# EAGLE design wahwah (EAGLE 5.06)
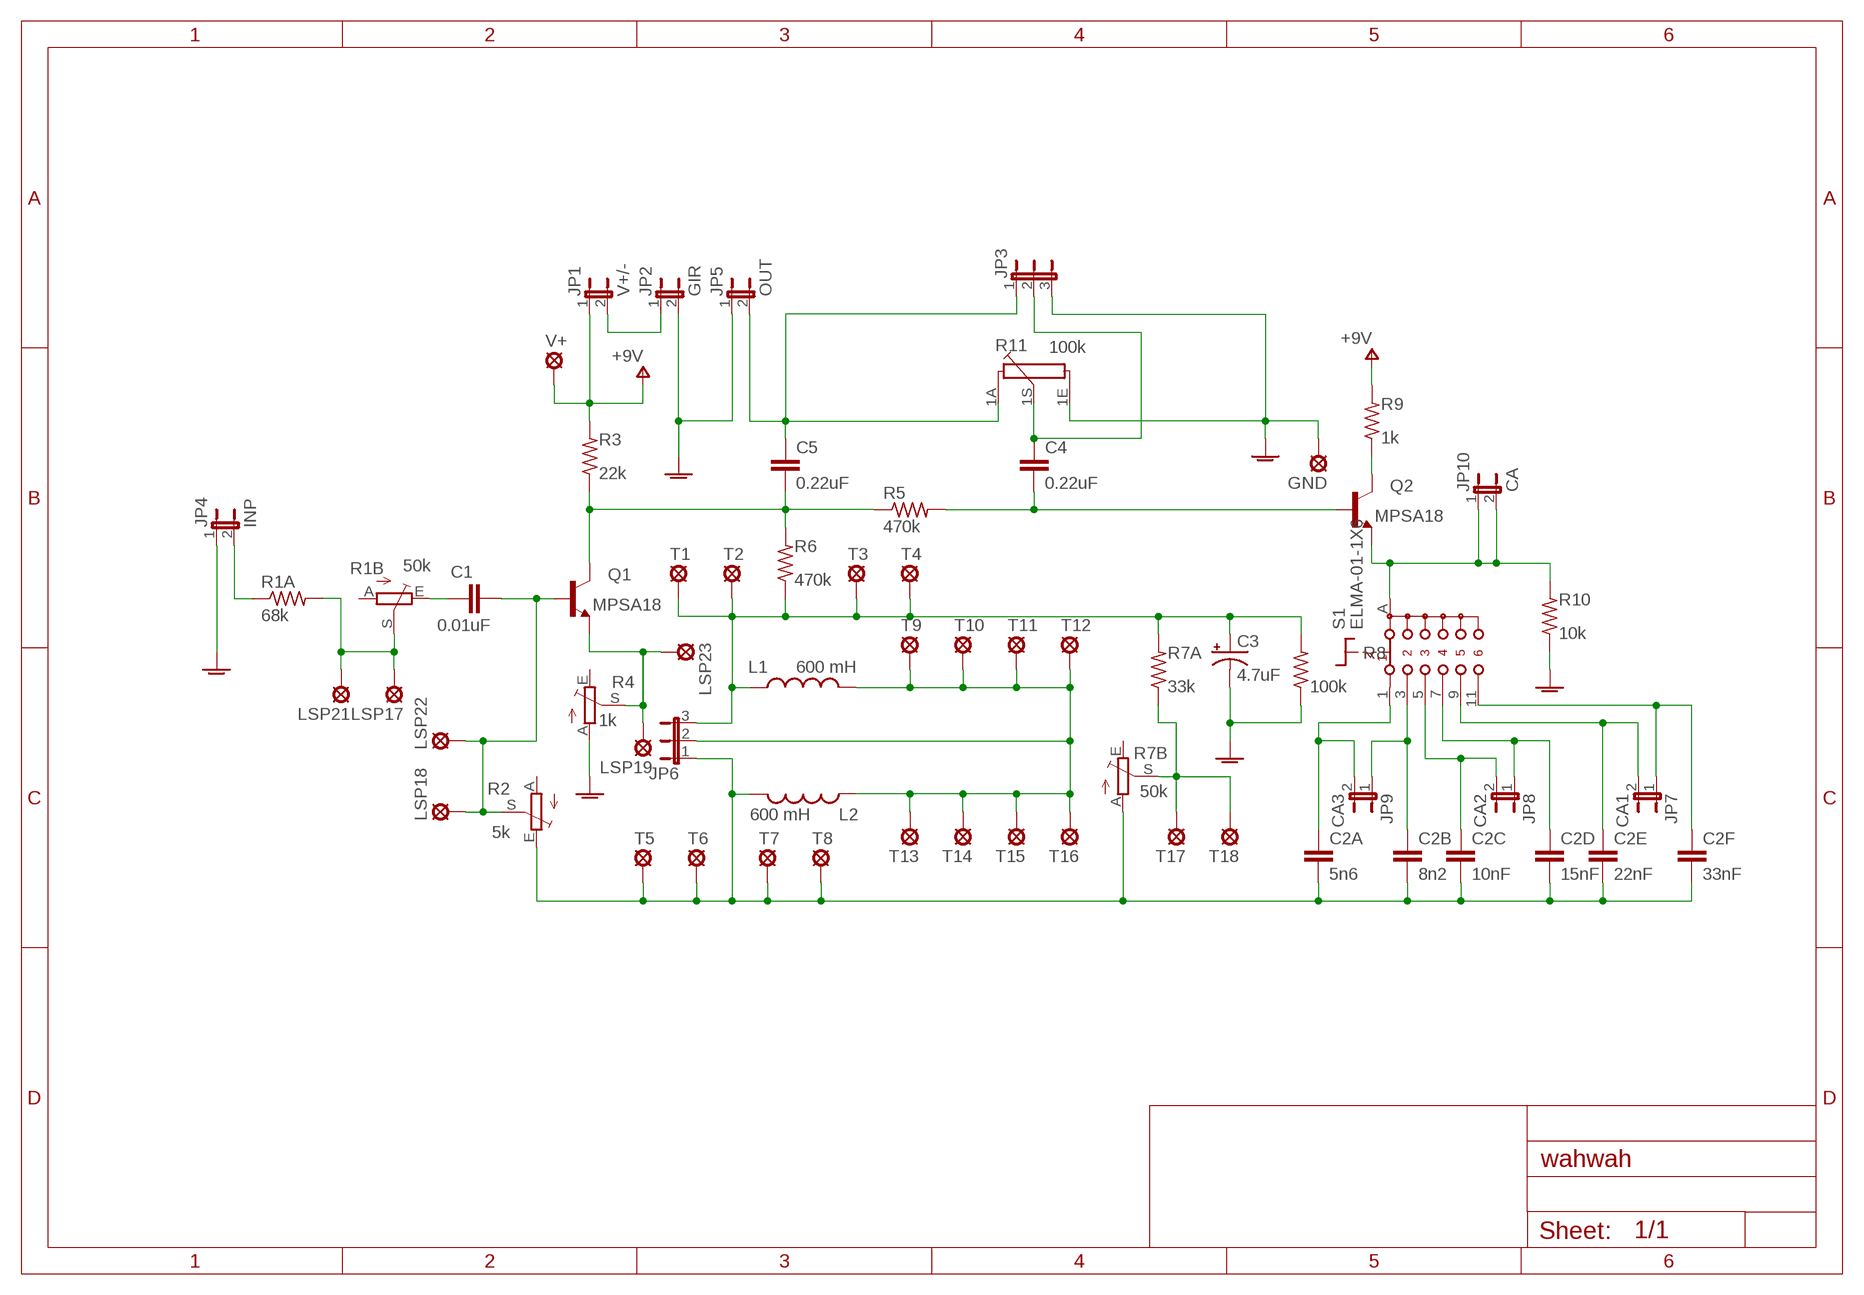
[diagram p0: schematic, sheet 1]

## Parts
C1  0.01uF  C-EU050-025X075  [C050-025X075]
C2A  5n6  C-EU050-025X075  [C050-025X075]
C2B  8n2  C-EU050-025X075  [C050-025X075]
C2C  10nF  C-EU050-025X075  [C050-025X075]
C2D  15nF  C-EU050-025X075  [C050-025X075]
C2E  22nF  C-EU050-025X075  [C050-025X075]
C2F  33nF  C-EU050-025X075  [C050-025X075]
C3  4.7uF  CPOL-USE2.5-7  [E2,5-7]
C4  0.22uF  C-EU050-025X075  [C050-025X075]
C5  0.22uF  C-EU050-025X075  [C050-025X075]
GND  MCS10B  [MCS10B]
JP1  V+/-  JP1E  [JP1]
JP2  GIR  JP1E  [JP1]
JP3  JP2E  [JP2]
JP4  INP  JP1E  [JP1]
JP5  OUT  JP1E  [JP1]
JP6  JP2E  [JP2]
JP7  CA1  JP1E  [JP1]
JP8  CA2  JP1E  [JP1]
JP9  CA3  JP1E  [JP1]
JP10  CA  JP1E  [JP1]
L1  600 mH  L-USTJ3-U2  [TJ3-U2]
L2  600 mH  L-USTJ3-U2  [TJ3-U2]
LSP17  MCS10B  [MCS10B]
LSP18  MCS10B  [MCS10B]
LSP19  MCS10B  [MCS10B]
LSP21  MCS10B  [MCS10B]
LSP22  MCS10B  [MCS10B]
LSP23  MCS10B  [MCS10B]
Q1  MPSA18  -NPN-TO92-EBC  [TO92-EBC]
Q2  MPSA18  -NPN-TO92-EBC  [TO92-EBC]
R1A  68k  R-US_0207/10  [0207/10]
R1B  50k  TRIM_EU-S64W  [S64W]
R2  5k  TRIM_EU-S64W  [S64W]
R3  22k  R-US_0207/10  [0207/10]
R4  1k  TRIM_EU-S64W  [S64W]
R5  470k  R-US_0207/10  [0207/10]
R6  470k  R-US_0207/10  [0207/10]
R7A  33k  R-US_0207/10  [0207/10]
R7B  50k  TRIM_EU-S64W  [S64W]
R8  100k  R-US_0207/10  [0207/10]
R9  1k  R-US_0207/10  [0207/10]
R10  10k  R-US_0207/10  [0207/10]
R11  100k  PC16S  [PC16S]
S1  ELMA-01-1X6  [ELMA-01-1X6]
T1  MCS10B  [MCS10B]
T2  MCS10B  [MCS10B]
T3  MCS10B  [MCS10B]
T4  MCS10B  [MCS10B]
T5  MCS10B  [MCS10B]
T6  MCS10B  [MCS10B]
T7  MCS10B  [MCS10B]
T8  MCS10B  [MCS10B]
T9  MCS10B  [MCS10B]
T10  MCS10B  [MCS10B]
T11  MCS10B  [MCS10B]
T12  MCS10B  [MCS10B]
T13  MCS10B  [MCS10B]
T14  MCS10B  [MCS10B]
T15  MCS10B  [MCS10B]
T16  MCS10B  [MCS10B]
T17  MCS10B  [MCS10B]
T18  MCS10B  [MCS10B]
V+  MCS10B  [MCS10B]

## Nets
AGND: C3.- GND.MP JP2.2 JP3.3 JP4.1 JP5.1 R4.A R8.1 R10.1 R11.1E
N$1: C1.1 R1B.E
N$3: LSP19.MP LSP23.MP Q1.E R4.S
N$4: C3.+ JP6.3 L1.1 R6.1 R7A.2 R8.2 T1.MP T2.MP T3.MP T4.MP
N$5: C2A.1 C2B.1 C2C.1 C2D.1 C2E.1 C2F.1 JP6.1 L2.2 R2.E R7B.A T5.MP T6.MP T7.MP T8.MP
N$6: C5.1 Q1.C R3.1 R5.1 R6.2
N$7: C4.1 Q2.B R5.2
N$8: JP10.1 JP10.2 Q2.E R10.2 S1.A(S)
N$9: C5.2 JP3.1 JP5.2 R11.1A
N$10: Q2.C R9.1
N$11: C4.2 JP3.2 R11.1S
N$12: JP6.2 L1.2 L2.1 T9.MP T10.MP T11.MP T12.MP T13.MP T14.MP T15.MP T16.MP
N$13: R7A.1 R7B.S T17.MP T18.MP
N$14: LSP17.MP LSP21.MP R1A.2 R1B.S
N$15: JP4.2 R1A.1
N$16: C2A.2 JP9.2 S1.1
N$17: JP1.2 JP2.1
N$18: C2B.2 JP9.1 S1.3
N$19: C2C.2 JP8.2 S1.5
N$20: C2D.2 JP8.1 S1.7
N$21: C2E.2 JP7.2 S1.9
N$22: C2F.2 JP7.1 S1.11
N$23: C1.2 LSP18.MP LSP22.MP Q1.B R2.S
V+: JP1.1 R3.2 R9.2 V+.MP ; supply symbol labelled +9V
Unconnected: R1B.A R2.A R4.E R7B.E

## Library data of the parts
C1 C2A C2B C2C C2D C2E C2F C4 C5 = resistor:C-EU: CAPACITOR, European symbol
C3 = rcl:CPOL-US: POLARIZED CAPACITOR, American symbol
GND LSP17-LSP19 LSP21-LSP23 T1-T18 V+ = solpad:MCS10B: SOLDER PAD
JP1 JP2 JP4 JP5 JP7-JP10 = jumper:JP1E: JUMPER
JP3 JP6 = jumper:JP2E: JUMPER
L1 L2 = resistor:L-US: INDUCTOR, American symbol
Q1 Q2 = transistor-neu-to92:*-NPN-: NPN Transistror
R1A R3 R5 R6 R7A R8-R10 = resistor:R-US_: RESISTOR, American symbol
R1B R2 R4 R7B = pot:TRIM_EU-: POTENTIOMETER
R11 = piher:PC16S: POTENTIOMETER single carbon potentiometer, 16 mm, S3ROH
S1 = switch:ELMA-01-1X6: Rotary Switches Type 01 Source: http://www.elma.com/files/products/rotary_components/pdfs/rotary_switches_type_01_002.pdf

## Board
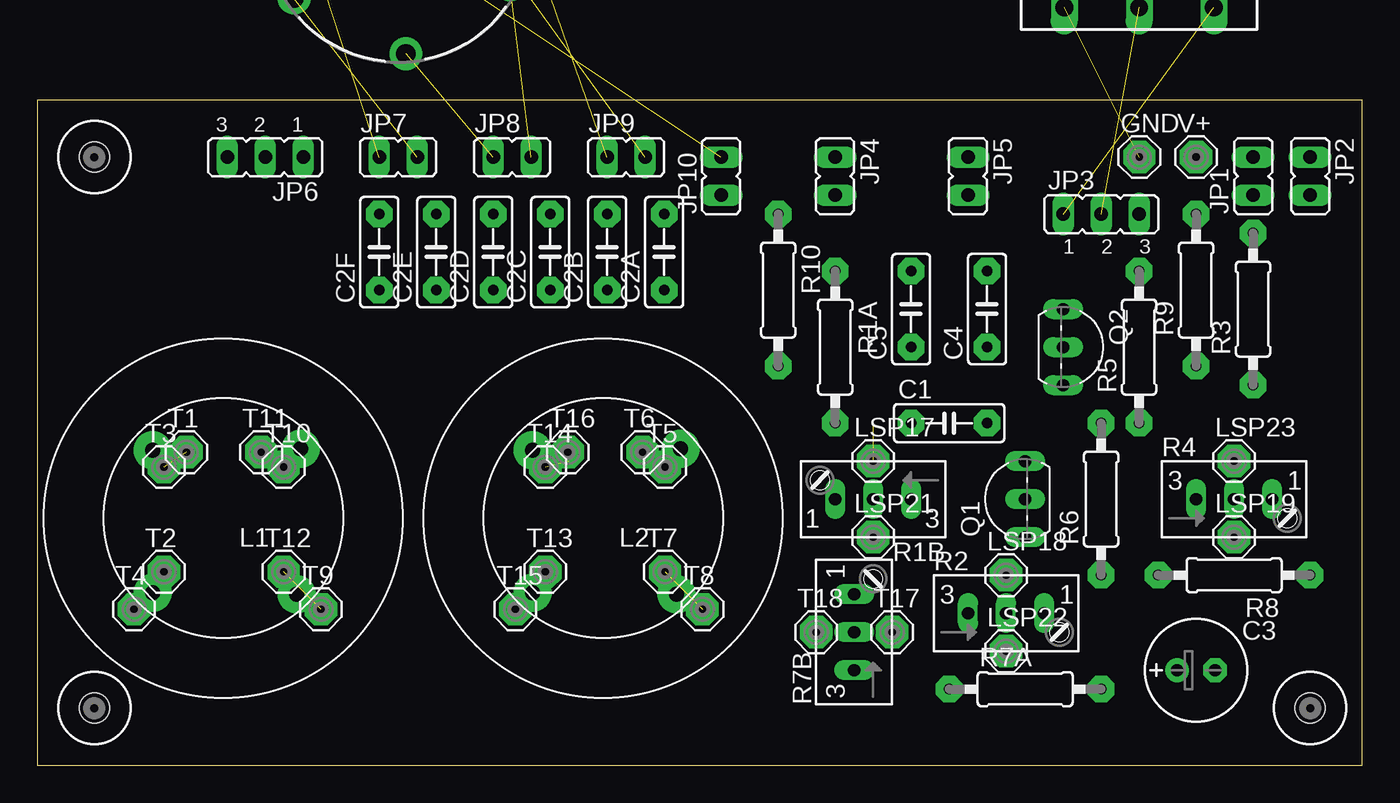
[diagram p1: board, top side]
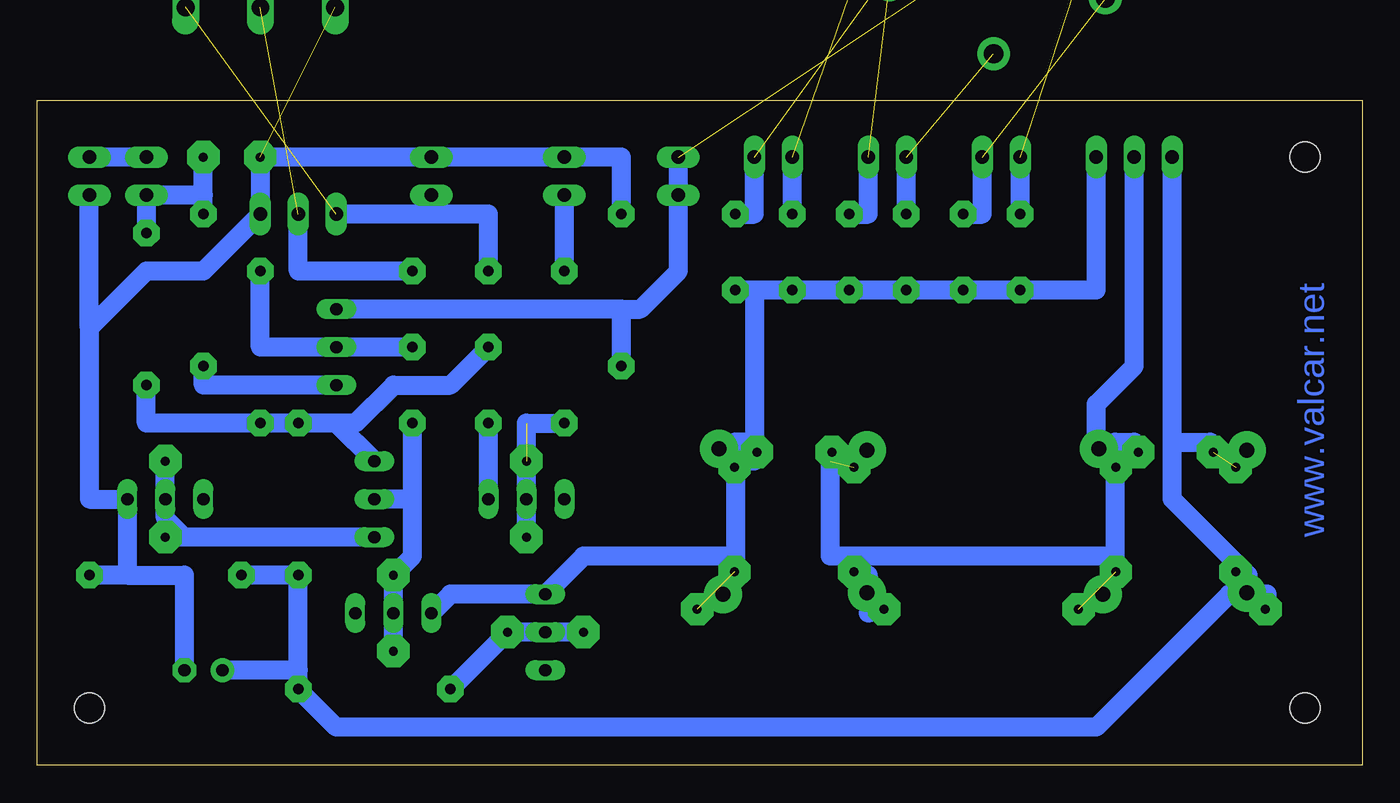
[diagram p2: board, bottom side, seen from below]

Size 88.57 x 44.44 mm. Coordinates in mm from the lower left corner, seen from the top.
Outline: 0,0 88.57,0 88.57,44.44 0,44.44 0,0
Copper layers 16: Bottom 0.035mm
Design rules "default *": minimum track width 50mil, minimum drill 24mil, track to track 16mil, track to pad 16mil, pad to pad 16mil, via to via 16mil, smd to smd 8mil, copper to edge 40mil, drill to drill 8mil, minimum pad ring 10mil, minimum via ring 8mil, stop-mask expansion 4mil, vias tented up to drill 0mil, thermal gap 10mil

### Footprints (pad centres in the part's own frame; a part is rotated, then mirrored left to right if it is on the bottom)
C050-025X075 = drill 0.7 pad 1.778 octagon: 1 -2.54,0; 2 2.54,0
E2,5-7 = drill 0.813 pad 1.6 round: + -1.27,0 | drill 0.813 pad 1.6 octagon: - 1.27,0
MCS10B = drill 0.6 pad 2.159 octagon: MP 0,0
JP1 = drill 0.914 long: 1 0,-1.27; 2 0,1.27
JP2 = drill 0.914 long: 1 -2.54,0; 2 0,0; 3 2.54,0
TJ3-U2 = drill 1 pad 2.54 round: 1 3.73,5; 2 -6.16,-4.62; 3 -5.89,5.08; 4 3.73,-4.54
TO92-EBC = drill 0.813 long: B 0,-1.27; C 2.54,-1.27; E -2.54,-1.27
0207/10 = drill 0.7 pad 1.778 octagon: 1 -5.08,0; 2 5.08,0
S64W = drill 0.813 long: A 2.54,1.27; E -2.54,1.27; S 0,1.27
PC16S = drill 1.2 long: 1A -5,6.5; 1E 5,6.5; 1S 0,6.5
ELMA-01-1X6 = drill 1.3 pad 2.184 round: 1 -0.51,8.334; 3 6.963,4.609; 5 7.473,-3.726; 7 0.51,-8.334; 9 -6.963,-4.609; 11 -7.473,3.726 | drill 1.5 pad 2.54 round: A 2.652,-2.652
DRIL-2 = hole 2: 0,0

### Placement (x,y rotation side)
C1  60.96,22.86 0 top
C2A  41.91,34.29 90 top
C2B  38.1,34.29 90 top
C2C  34.29,34.29 90 top
C2D  30.48,34.29 90 top
C2E  26.67,34.29 90 top
C2F  22.86,34.29 90 top
C3  77.47,6.35 0 top
C4  63.5,30.48 90 top
C5  58.42,30.48 90 top
GND  73.67,40.64 0 top
JP1  81.28,39.37 0 top
JP2  85.09,39.37 180 top
JP3  71.12,36.83 0 top
JP4  53.34,39.37 180 top
JP5  62.23,39.37 180 top
JP6  15.24,40.64 180 top
JP7  24.13,40.64 270 top
JP8  31.75,40.64 270 top
JP9  39.37,40.64 270 top
JP10  45.72,39.37 0 top
L1  11.43,16.51 180 top
L2  36.83,16.51 180 top
LSP17  55.88,20.32 0 top
LSP18  64.77,12.7 0 top
LSP19  80.01,15.24 0 top
LSP21  55.88,15.24 0 top
LSP22  64.77,7.62 0 top
LSP23  80.01,20.32 0 top
Q1  64.77,17.78 90 top
Q2  69.85,27.94 270 top
R1A  53.34,27.94 270 top
R1B  55.88,19.05 180 top
R2  64.77,8.89 0 top
R3  81.28,30.48 90 top
R4  80.01,16.51 0 top
R5  73.66,27.94 90 top
R6  71.12,17.78 90 top
R7A  66.04,5.08 0 top
R7B  55.88,8.89 90 top
R8  80.01,12.7 180 top
R9  77.47,31.75 90 top
R10  49.53,31.75 270 top
R11  not placed on the board
S1  not placed on the board
T1  9.96,20.92 0 top
T2  8.46,12.92 0 top
T3  8.46,19.92 0 top
T4  6.46,10.42 0 top
T5  41.96,19.92 0 top
T6  40.46,20.92 0 top
T7  41.96,12.92 0 top
T8  44.46,10.42 0 top
T9  18.96,10.42 0 top
T10  16.46,19.92 0 top
T11  14.96,20.92 0 top
T12  16.46,12.92 0 top
T13  33.96,12.92 0 top
T14  33.96,19.92 0 top
T15  31.96,10.42 0 top
T16  35.46,20.92 0 top
T17  57.15,8.89 0 top
T18  52.07,8.89 0 top
U$1  [DRIL-2]  85.09,3.81 0 top
U$2  [DRIL-2]  3.81,3.81 0 top
U$3  [DRIL-2]  3.81,40.64 0 top
V+  77.47,40.64 0 top

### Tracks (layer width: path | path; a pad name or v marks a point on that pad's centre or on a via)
AGND  (1 unrouted)
  Bottom 1.27: 82.55,12.7 R4.A 85.09,17.78 85.09,29.21 | 82.55,12.7 R8.1 | C3.- 78.74,12.7 82.55,12.7 | GND.MP JP3.3 77.47,33.02 81.28,33.02 85.09,29.21 | 85.09,29.21 JP2.2 | R10.1 49.53,40.64 JP4.1 JP5.1 GND.MP | GND.MP
N$1
  Bottom 1.27: R1B.E C1.1
N$3
  Bottom 1.27: Q1.E 78.74,15.24 | 78.74,15.24 80.01,16.51 R4.S LSP23.MP | 78.74,15.24 LSP19.MP
N$4  (1 unrouted)
  Bottom 1.27: R6.1 R8.2 R6.1 | 71.12,6.35 R7A.2 68.58,2.54 17.78,2.54 8.89,11.43 L1.1 | 71.12,6.35 R6.1 | 71.12,6.35 C3.+ | 7.62,12.7 12.7,17.78 12.7,21.59 | 12.7,21.59 JP6.3 | 7.62,12.7 8.46,13.54 | T4.MP 6.35,11.43 7.62,11.43 L1.1 | L1.1 7.62,12.7 | 7.62,12.7 T2.MP | 12.7,21.59 10.16,21.59 T1.MP
N$5  (1 unrouted)
  Bottom 1.27: R2.E 60.96,11.43 R7B.A 52.07,13.97 41.91,13.97 | 40.64,31.75 C2B.1 C2C.1 C2D.1 C2E.1 C2F.1 17.78,31.75 JP6.1 | 40.64,31.75 C2A.1 | 40.64,21.59 41.91,21.59 L2.2 | 41.91,13.97 41.91,19.05 T5.MP 41.91,20.32 40.64,20.32 T6.MP 40.64,21.59 | 41.91,13.97 T7.MP | 40.64,31.75 40.64,21.59
N$6
  Bottom 1.27: Q1.C 68.58,22.86 67.31,22.86 | 67.31,22.86 R6.2 R5.1 81.28,22.86 R3.1 | C5.1 60.96,25.4 64.77,25.4 67.31,22.86
N$7
  Bottom 1.27: C4.1 Q2.B 73.66,27.94 R5.2
N$8  (1 unrouted)
  Bottom 1.27: 49.53,30.48 Q2.E | R10.2 49.53,30.48 | JP10.2 JP10.1 45.72,33.02 48.26,30.48 49.53,30.48
N$9  (1 unrouted)
  Bottom 1.27: C5.2 58.42,36.83 62.23,36.83 | 62.23,36.83 JP3.1 | 62.23,36.83 JP5.2
N$10
  Bottom 1.27: Q2.C 77.47,25.4 R9.1
N$11  (1 unrouted)
  Bottom 1.27: JP3.2 71.12,33.02 C4.2
N$12  (2 unrouted)
  Bottom 1.27: JP6.2 15.24,26.67 17.78,24.13 17.78,21.59 L1.2 16.51,21.59 | 16.51,21.59 15.24,21.59 T11.MP | 16.51,21.59 16.51,20.32 T10.MP 16.51,19.05 16.51,13.97 | T15.MP 33.02,10.16 33.02,11.43 L2.1 33.02,12.7 T13.MP 34.29,13.97 | 34.29,13.97 35.56,13.97 35.56,20.32 T16.MP | 16.51,13.97 34.29,13.97 | T12.MP 16.51,13.97
N$13
  Bottom 1.27: R7A.1 T17.MP R7B.S T18.MP
N$14  (1 unrouted)
  Bottom 1.27: R1A.2 55.88,22.86 R1B.S LSP21.MP
N$15
  Bottom 1.27: R1A.1 JP4.2
N$16  (1 unrouted)
  Bottom 1.27: JP9.2 40.64,36.83 C2A.2
N$17
  Bottom 1.27: JP1.2 JP2.1
N$18  (1 unrouted)
  Bottom 1.27: C2B.2 JP9.1
N$19  (1 unrouted)
  Bottom 1.27: JP8.2 33.02,36.83 C2C.2
N$20  (1 unrouted)
  Bottom 1.27: C2D.2 JP8.1
N$21  (1 unrouted)
  Bottom 1.27: JP7.2 25.4,36.83 C2E.2
N$22  (1 unrouted)
  Bottom 1.27: C2F.2 JP7.1
N$23
  Bottom 1.27: 63.5,17.78 63.5,13.97 LSP18.MP R2.S LSP22.MP | 63.5,17.78 Q1.B | 63.5,17.78 C1.2
V+
  Bottom 1.27: R9.2 77.47,38.1 | 77.47,38.1 V+.MP | 77.47,38.1 JP1.1 R3.2

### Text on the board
Bottom: www.valcar.net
